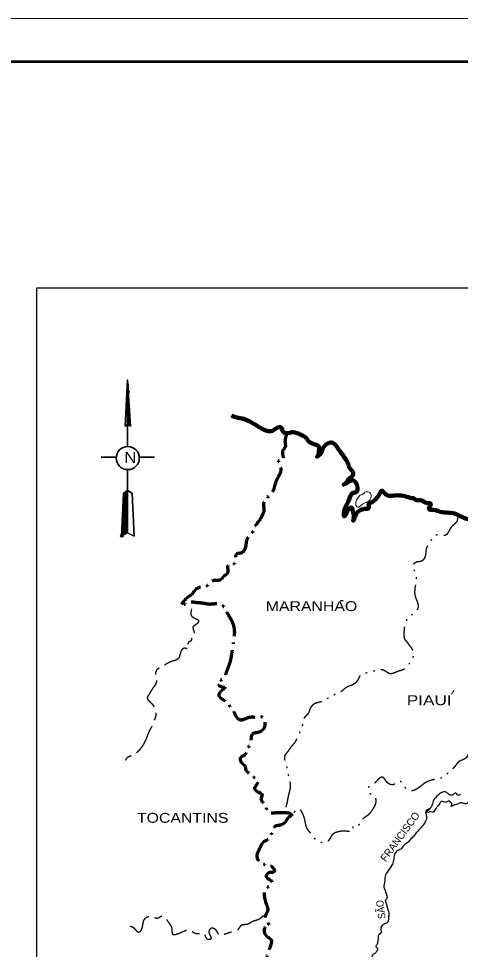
# Model space of a CAD drawing. Extents: x 512883 to 1063249, y 8784064 to 9081064.
# Drawn here: x 950481 to 1001709, y 8973228 to 9081064 of the extents above; entities that cross this region are included whole.
import ezdxf

# ---------------------------------------------------------------- set-up
doc = ezdxf.new("R2010")
doc.units = 0
doc.header["$LTSCALE"] = 600
doc.header["$PDMODE"] = 32
doc.header["$PDSIZE"] = 300
for name, pattern in [('DASH_DOUBLE_DOT', [9.2, 5, -1.2, 0.3, -1.2, 0.3, -1.2]), ('DOT_DASHED', [7.7, 5, -1.2, 0.3, -1.2]), ('LONG_DASH_SHORT_DASH', [9.9, 6, -1.2, 1.5, -1.2])]:
    doc.linetypes.add(name, pattern=pattern)
for name, color, linetype, lineweight in [('1', 7, 'Continuous', 25), ('3', 7, 'Continuous', 25), ('30', 7, 'Continuous', 25)]:
    doc.layers.add(name, color=color, linetype=linetype, lineweight=lineweight)

msp = doc.modelspace()

# ---------------------------------------------------------------- linework, layer by layer
at = {"layer": '1', "lineweight": 13}
for points in [[(512883.1, 8784063.9), (1063248.6, 8784063.9), (1063248.6, 9081063.9), (512883.1, 9081063.9)], [(537883.1, 9076063.9), (1058248.6, 9076063.9), (1058248.6, 8789063.9), (537883.1, 8789063.9)]]:
    msp.add_lwpolyline(points, close=True, dxfattribs=at)
at = {"layer": '1', "lineweight": 53}
msp.add_lwpolyline([(537883.1, 8789063.9), (1058248.6, 8789063.9), (1058248.6, 9076063.9), (537883.1, 9076063.9)], close=True, dxfattribs=at)
at = {"layer": '1'}
msp.add_lwpolyline([(537883.1, 9076063.9), (1058248.6, 9076063.9), (1058248.6, 8789063.9), (537883.1, 8789063.9)], close=True, dxfattribs=at)
at = {"layer": '3'}
msp.add_lwpolyline([(537883.1, 9076063.9), (1058248.6, 9076063.9), (1058248.6, 8789063.9), (537883.1, 8789063.9)], close=True, dxfattribs=at)
at = {"layer": '30'}
for p, q in [((963115.9, 9039189), (963170.4, 9037281.1)), ((963170.4, 9038698.4), (963170.4, 9037281.1)), ((963224.9, 9037281.1), (963170.4, 9038698.4)), ((963170.4, 9037826.2), (963170.4, 9037281.1)), ((963224.9, 9037281.1), (963170.4, 9037826.2)), ((963115.9, 9034010.5), (963443, 9033847)), ((962407.3, 9021091.6), (963115.9, 9021473.2)), ((963115.9, 9021473.2), (963879.1, 9021091.6)), ((998111.5, 8989475.7), (997675.4, 8989039.6))]:
    msp.add_line(p, q, dxfattribs=at)
at = {"layer": '30', "lineweight": 35}
for p, q in [((963170.4, 9037281.1), (963170.4, 9034065)), ((963170.4, 9037281.1), (963224.9, 9034065)), ((963170.4, 9037281.1), (963224.9, 9034065)), ((963334, 9033956), (963224.9, 9037281.1)), ((963388.5, 9033901.5), (963224.9, 9037281.1)), ((963115.9, 9031503), (963115.9, 9034010.5)), ((961807.7, 9030249.3), (960063.3, 9030249.3)), ((964478.7, 9030249.3), (966223, 9030249.3)), ((962625.3, 9026052), (962407.3, 9021091.6)), ((962461.8, 9021146.1), (962625.3, 9025943)), ((963115.9, 9026433.6), (962625.3, 9026052))]:
    msp.add_line(p, q, dxfattribs=at)
at = {"layer": '30', "lineweight": 13}
for p, q in [((963170.4, 9034065), (963388.5, 9033901.5)), ((963224.9, 9034065), (963334, 9033956)), ((963224.9, 9034065), (963334, 9034010.5)), ((963115.9, 9026433.6), (962625.3, 9026052)), ((962625.3, 9025943), (962679.8, 9025997.5)), ((963006.9, 9021527.7), (962625.3, 9021309.6)), ((962952.4, 9021527.7), (962679.8, 9021364.1)), ((962897.9, 9021527.7), (962734.3, 9021418.7)), ((962843.4, 9021527.7), (962788.8, 9021527.7)), ((963115.9, 9021473.2), (962516.3, 9021200.6)), ((963061.4, 9021473.2), (962570.8, 9021255.1))]:
    msp.add_line(p, q, dxfattribs=at)
at = {"layer": '30'}
msp.add_lwpolyline([(952595.4, 9049873), (1052567.1, 9049873), (1052567.1, 8921774), (952595.4, 8921774)], close=True, dxfattribs=at)
msp.add_lwpolyline([(952595.4, 9049873), (1052567.1, 9049873), (1052567.1, 8921774), (952595.4, 8921774)], close=True, dxfattribs=at)
at = {"layer": '30', "lineweight": 35}
for points in [[(963443, 9033847), (963115.9, 9039189), (962843.4, 9033847), (963115.9, 9034010.5), (963115.9, 9039189)], [(963334, 9034010.5), (963224.9, 9035863.8), (963279.4, 9034065)], [(963115.9, 9028832), (963115.9, 9026433.6), (963115.9, 9021473.2)], [(962516.3, 9021200.6), (962679.8, 9025943), (963115.9, 9026324.6), (963061.4, 9021473.2)], [(962570.8, 9021255.1), (962734.3, 9025943), (963061.4, 9026215.6), (963006.9, 9021527.7)], [(962625.3, 9021309.6), (962788.8, 9025943), (963006.9, 9026161), (962952.4, 9021527.7)], [(962679.8, 9025997.5), (963115.9, 9026379.1), (963115.9, 9021473.2)], [(962679.8, 9021364.1), (962843.4, 9025943), (962952.4, 9026052), (962897.9, 9021527.7)], [(962734.3, 9021418.7), (962843.4, 9025834), (962897.9, 9025943), (962843.4, 9021527.7)], [(962788.8, 9021527.7), (962843.4, 9025888.5), (963061.4, 9026270.1)], [(963879.1, 9021091.6), (963661, 9026052), (963115.9, 9026433.6)]]:
    msp.add_lwpolyline(points, dxfattribs=at)
at = {"layer": '30', "lineweight": 13}
for points in [[(963279.4, 9034065), (963334, 9034065), (963279.4, 9034228.6), (963170.4, 9034065)], [(962407.3, 9021091.6), (963115.9, 9021473.2), (962461.8, 9021146.1)]]:
    msp.add_lwpolyline(points, dxfattribs=at)
at = {"layer": '30', "lineweight": 35}
msp.add_circle((963141, 9030146.2), 1339.3, dxfattribs=at)
at = {"layer": '30', "lineweight": 140}
for points in [[(975162.7, 9035100.7), (975871.3, 9034828.2), (976470.9, 9034719.1), (977561.1, 9034228.6), (978106.2, 9033901.5), (978651.3, 9033574.4), (979305.4, 9033301.9), (979905.1, 9033301.9), (980395.6, 9033628.9), (980940.7, 9033683.4), (981158.8, 9033192.8), (981594.9, 9033029.3), (982194.5, 9033138.3), (982794.1, 9033029.3), (983284.7, 9032811.3), (983775.3, 9032538.7), (984047.8, 9032157.2), (984429.4, 9031884.6), (985029, 9031666.6), (985247, 9031557.6), (985301.6, 9031012.4), (985192.5, 9030467.3), (985083.5, 9030303.8), (985410.6, 9030576.4), (985683.1, 9031067), (985955.7, 9031557.6), (986446.3, 9031884.6), (986827.8, 9031939.1), (987263.9, 9031612.1), (987536.5, 9031230.5), (987863.5, 9030794.4), (988354.1, 9030085.8), (988681.2, 9029486.2), (988953.7, 9028886.6), (989226.3, 9028559.5), (989280.8, 9028232.4), (988899.2, 9027850.8), (988681.2, 9027632.8), (988354.1, 9027196.7), (988190.6, 9027087.7), (988681.2, 9027360.3), (989171.8, 9027578.3), (989444.3, 9027469.3), (989662.4, 9027142.2), (989771.4, 9026760.7), (989716.9, 9026270.1), (989280.8, 9026106.5), (988844.7, 9025506.9), (988681.2, 9025070.8), (988190.6, 9023762.6), (988245.1, 9023381), (988408.6, 9023599.1), (988790.2, 9024307.7), (989062.8, 9024416.7), (989226.3, 9024035.1), (989335.3, 9023653.6), (989335.3, 9023272), (989280.8, 9022890.4), (989498.8, 9023381), (989716.9, 9023817.1), (990153, 9024144.2), (990643.6, 9024253.2), (991079.6, 9024362.2), (991079.6, 9024798.3), (991515.7, 9025070.8), (991897.3, 9025397.9), (992333.4, 9025997.5), (992605.9, 9026379.1), (992987.5, 9025997.5), (993587.1, 9025779.5), (994404.8, 9025834), (995004.4, 9025779.5), (995385.9, 9025725)], [(995385.9, 9025670.5), (995658.5, 9025615.9), (996094.6, 9025506.9), (996258.1, 9025506.9), (996367.1, 9025452.4)], [(996367.1, 9025452.4), (996476.1, 9025343.4), (997184.8, 9025234.4), (997784.4, 9024961.8), (998275, 9024852.8), (998056.9, 9024253.2), (998602, 9024144.2), (999365.2, 9023926.1), (1000400.9, 9023817.1), (1001218.5, 9023653.6), (1001763.6, 9023381), (1002472.3, 9023108.5), (1003126.4, 9022999.5), (1003889.5, 9023163), (1004543.7, 9023217.5), (1005633.9, 9023381)]]:
    msp.add_spline(points, degree=3, dxfattribs=at)
at = {"layer": '30', "linetype": 'DOT_DASHED', "lineweight": 70}
for points in [[(981594.9, 9033029.3), (981376.8, 9031939.1), (981376.8, 9031394), (981158.8, 9031121.5), (981104.3, 9030521.8), (981049.8, 9029867.7), (980613.7, 9029813.2), (980722.7, 9029431.7), (980886.2, 9028886.6), (980777.2, 9028341.4), (980450.2, 9027741.8), (980232.1, 9027196.7), (980014.1, 9026433.6), (979687, 9025888.5), (979087.4, 9025397.9), (978869.3, 9024743.8), (978923.9, 9024144.2), (978760.3, 9023599.1), (978324.2, 9022835.9), (977888.2, 9022236.3), (977506.6, 9021418.7), (977016, 9020873.6), (976798, 9019892.4), (976252.9, 9019129.2), (975816.8, 9019074.7), (975598.7, 9018366.1), (975435.2, 9017875.5), (974781.1, 9017766.5), (974726.6, 9016894.3), (974236, 9016403.7), (973854.4, 9016022.1), (973200.3, 9015967.6), (972764.2, 9015804.1), (972273.6, 9015313.5), (971456, 9015150), (970965.4, 9014877.4), (970583.8, 9014386.8), (969820.7, 9013787.2), (969275.6, 9012969.6), (970147.7, 9013460.2), (970910.9, 9013460.2), (971946.6, 9013351.1), (972655.2, 9013242.1), (973309.3, 9013296.6), (974181.5, 9013024.1), (974726.6, 9012097.4), (975217.2, 9011225.2), (975489.7, 9010189.6), (975435.2, 9009208.4), (975162.7, 9007409.5), (974944.6, 9006373.8), (974563.1, 9005338.1), (974127, 9004520.5), (973527.3, 9004084.4), (973799.9, 9003757.3), (974399.5, 9003539.3), (973963.4, 9003157.7), (973690.9, 9002612.6), (974290.5, 9002122), (974999.1, 9001358.9), (975435.2, 9000759.3), (975871.3, 8999996.2), (976307.4, 8999832.6), (977125, 9000105.2), (978160.7, 9000159.7), (978760.3, 9000159.7), (979032.9, 8999560.1), (978814.8, 8998687.9), (978269.7, 8998360.8), (977615.6, 8998197.3), (977343.1, 8997052.6), (976907, 8996289.5), (976743.5, 8995798.9), (976198.3, 8995417.3), (976361.9, 8994817.7), (976743.5, 8994436.1), (976798, 8994054.5), (977343.1, 8993563.9), (977670.1, 8993236.9), (978160.7, 8992909.8), (978106.2, 8992364.7), (977833.7, 8991874.1), (978324.2, 8991438.1), (978705.8, 8991165.5), (978596.8, 8990674.9), (978760.3, 8990293.3), (979141.9, 8989857.2), (979250.9, 8989312.2), (980559.2, 8989094.1), (981267.8, 8989094.1), (981867.4, 8989039.6)], [(981867.4, 8989039.6), (982140, 8988821.6), (981758.4, 8988494.5), (981376.8, 8987949.4), (980831.7, 8987622.3), (980177.6, 8987458.8), (979850.5, 8986859.2), (979469, 8985987), (978869.3, 8985660), (978433.3, 8984951.3), (978106.2, 8984024.7), (978433.3, 8983316), (979196.4, 8983043.5), (979959.6, 8982716.4), (980123.1, 8982225.8), (979414.5, 8982062.3), (979196.4, 8981626.2), (979850.5, 8981081.1), (979741.5, 8980754.1), (979032.9, 8980154.4), (978978.4, 8979336.8), (979196.4, 8978464.6), (979359.9, 8977756), (979087.4, 8977101.9), (979359.9, 8976338.7), (979523.5, 8975902.6), (979196.4, 8975848.1), (979087.4, 8974921.5), (979741.5, 8974376.4), (979632.5, 8973504.2), (979305.4, 8972577.5), (979196.4, 8971759.9), (979359.9, 8971051.2), (979741.5, 8970288.1), (980286.6, 8969688.5), (980341.1, 8968707.3), (980068.6, 8967726.1), (979905.1, 8966690.4), (979850.5, 8966036.3), (979469, 8965164.1), (987645.5, 8970724.2), (988572.2, 8969415.9), (989389.8, 8969034.4), (989498.8, 8968380.2), (989716.9, 8967726.1), (990425.5, 8967344.5), (991079.6, 8966854), (991515.7, 8966690.4), (992224.3, 8967181), (992714.9, 8967617.1), (993205.5, 8967235.5), (993805.1, 8966963), (994568.3, 8966417.9), (995167.9, 8965872.8), (995658.5, 8965382.2), (996367.1, 8965109.6), (996803.2, 8965109.6), (997511.8, 8964673.5), (998166, 8965000.6), (999038.1, 8965000.6), (999746.8, 8964237.5), (1000291.9, 8963528.8), (1000673.4, 8962874.7), (1000782.5, 8962220.6), (1000837, 8961621), (1001218.5, 8961675.5), (1001872.7, 8961675.5), (1002744.8, 8961730), (1003562.5, 8961566.5), (1004162.1, 8961348.4), (1004816.2, 8961184.9), (1005524.8, 8961021.4), (1006069.9, 8960639.8), (1006560.5, 8960149.2), (1007051.1, 8959658.6), (1007214.7, 8959113.5), (1006996.6, 8958077.8), (1006506, 8957369.2), (1006124.5, 8956769.6), (1005361.3, 8956551.5), (1004816.2, 8955842.9), (1004271.1, 8954807.2), (1003944, 8953717), (1003944, 8953171.9), (1004434.6, 8952354.2), (1004925.2, 8951918.2), (1005252.3, 8951046), (1005906.4, 8950609.9), (1006506, 8949955.8), (1007214.7, 8949737.8), (1008195.8, 8949901.3)]]:
    msp.add_spline(points, degree=3, dxfattribs=at)
at = {"layer": '30', "lineweight": 13}
msp.add_spline([(990643.6, 9026215.6), (991079.6, 9026215.6), (991297.7, 9026052), (991243.2, 9025343.4), (990807.1, 9025016.3), (990207.5, 9024689.3), (989825.9, 9024471.2), (989662.4, 9024580.2), (989607.9, 9025125.3), (989771.4, 9025452.4), (990098.5, 9025834), (990371, 9025943), (990643.6, 9026215.6)], degree=3, dxfattribs=at)
at = {"layer": '30', "linetype": 'DASH_DOUBLE_DOT'}
for points in [[(1001382.1, 9023490), (1001273, 9022781.4), (1000891.5, 9022399.8), (1000455.4, 9021854.7), (999964.8, 9021200.6), (999419.7, 9021200.6), (998820.1, 9021200.6), (998384, 9020764.5), (998002.4, 9020164.9), (997729.9, 9019565.3), (997675.4, 9019020.2), (997184.8, 9018202.6), (996639.7, 9018093.5), (996149.1, 9017657.5), (996367.1, 9017112.3), (996585.2, 9016458.2), (996421.6, 9014332.3), (996694.2, 9013514.7), (996803.2, 9012969.6), (996530.7, 9012370), (995767.5, 9011770.3), (995167.9, 9009535.4), (995222.4, 9009208.4), (995495, 9008881.3), (995713, 9008554.2), (996040.1, 9008118.2), (996203.6, 9007082.5), (995985.6, 9006537.4), (995549.5, 9006101.3), (995222.4, 9005719.7), (994513.8, 9005447.2), (993532.6, 9005174.6), (992824, 9005556.2), (991951.8, 9005556.2), (991025.1, 9005283.6), (990153, 9005011.1), (989716.9, 9004302.5), (989171.8, 9003866.4), (988517.7, 9003593.8), (987754.5, 9002994.2), (987100.4, 9002721.7), (986282.7, 9002285.6), (985519.6, 9001904), (984811, 9001686), (984320.4, 9001195.4), (984047.8, 9000541.2), (983557.2, 8999941.6), (983502.7, 8999396.5), (983393.7, 8999233), (983175.7, 8998578.9), (982848.6, 8997924.8), (982576.1, 8997325.2), (981976.4, 8996562), (981594.9, 8996016.9), (981322.3, 8995635.3), (981376.8, 8995035.7), (981540.3, 8994490.6), (981703.9, 8993727.5), (981812.9, 8993127.9), (981921.9, 8992691.8), (981976.4, 8992092.2), (981812.9, 8991274.5), (981649.4, 8990511.4), (981485.8, 8989802.7), (981104.3, 8989094.1)], [(1002908.3, 8996180.4), (1002690.3, 8995962.4), (1002417.8, 8995471.8), (1001545.6, 8994981.2), (1001000.5, 8994327.1), (1000346.4, 8993727.5), (999801.3, 8993236.9), (998711.1, 8992909.8), (997729.9, 8992582.8), (996748.7, 8991874.1), (995931, 8991601.6), (995385.9, 8991874.1), (995058.9, 8992364.7), (994731.8, 8992691.8), (994077.7, 8992364.7), (993314.6, 8992473.7), (992605.9, 8993182.4), (992224.3, 8992964.3), (991461.2, 8992255.7), (991025.1, 8991983.2), (991134.2, 8991383.5), (991788.3, 8990892.9), (991897.3, 8990456.9), (991788.3, 8989911.8), (991570.2, 8989530.2), (990970.6, 8988767.1), (990316.5, 8988221.9), (989880.4, 8987622.3), (989280.8, 8987567.8), (989226.3, 8986968.2), (988517.7, 8986913.7), (987591, 8986859.2), (986882.3, 8986532.1), (986228.2, 8985660), (985410.6, 8985660), (984756.5, 8986150.6), (984429.4, 8986586.6), (983938.8, 8987240.8), (983720.8, 8988003.9), (983393.7, 8989039.6), (983012.1, 8989475.7), (982576.1, 8989257.6), (982194.5, 8988821.6)]]:
    msp.add_spline(points, degree=3, dxfattribs=at)
at = {"layer": '30', "linetype": 'LONG_DASH_SHORT_DASH'}
for points in [[(970529.3, 9012697), (970529.3, 9011879.4), (971019.9, 9011552.3), (971347, 9011334.3), (971019.9, 9010843.7), (970692.8, 9010571.1), (970801.8, 9009862.5), (970529.3, 9009589.9), (970474.8, 9008990.3), (970147.7, 9008772.3), (970147.7, 9008009.1), (969766.2, 9008118.2), (969221.1, 9007518.6), (969003, 9006918.9), (968403.4, 9006646.4), (967858.3, 9006428.3), (967313.2, 9006101.3), (966931.6, 9005883.2), (966495.5, 9005610.7), (966386.5, 9004793), (966441, 9004138.9), (966114, 9003593.8), (965568.9, 9002721.7), (965405.3, 9002394.6), (965950.4, 9001686), (966277.5, 9001031.8), (966386.5, 9000323.2), (966168.5, 8999723.6), (966005, 8999233), (965623.4, 8998524.4), (965350.8, 8997815.7), (965023.8, 8997107.1), (964587.7, 8996453), (964097.1, 8995962.4), (963497.5, 8995635.3), (963061.4, 8995417.3), (962734.3, 8994817.7)], [(978869.3, 8977156.4), (978269.7, 8976665.8), (977615.6, 8976447.7), (976961.5, 8976120.7), (976307.4, 8976011.7), (975871.3, 8975466.6), (975053.6, 8975194), (974399.5, 8974976), (973799.9, 8974867), (973418.3, 8975412.1), (973145.8, 8975630.1), (972873.2, 8975684.6), (972546.2, 8975248.5), (972764.2, 8974430.9), (972437.2, 8974376.4), (972001.1, 8975030.5), (971347, 8975030.5), (970801.8, 8975139.5), (970256.7, 8975466.6), (969766.2, 8975357.5), (969384.6, 8975194), (968839.5, 8974976), (968403.4, 8974921.5), (968294.4, 8975575.6), (968130.8, 8976011.7), (967749.3, 8976556.8), (967422.2, 8976938.3), (967095.2, 8977047.4), (966604.6, 8976829.3), (965950.4, 8976992.8), (965350.8, 8976938.3), (965023.8, 8976665.8), (964751.2, 8975630.1), (964424.2, 8975194), (963933.6, 8975630.1), (963443, 8975902.6)]]:
    msp.add_spline(points, degree=3, dxfattribs=at)
at = {"layer": '30'}
for points in [[(997675.4, 8989039.6), (997838.9, 8989148.6), (997947.9, 8989094.1), (998166, 8989203.1), (998438.5, 8989148.6), (998656.6, 8989203.1), (998983.6, 8989693.7), (999310.7, 8990075.3), (999528.7, 8990402.3), (999746.8, 8990347.8), (999964.8, 8990293.3), (1000237.3, 8990402.3), (1000400.9, 8990456.9), (1000509.9, 8990293.3), (1000673.4, 8990184.3), (1000618.9, 8989802.7), (1000946, 8989966.3), (1001109.5, 8990020.8), (1001491.1, 8990129.8), (1001818.1, 8990238.8), (1002036.2, 8990184.3), (1002417.8, 8990129.8), (1002744.8, 8990347.8), (1003071.9, 8990347.8), (1003398.9, 8990456.9), (1003617, 8990729.4), (1003726, 8991056.5), (1003780.5, 8991220), (1003944, 8991601.6), (1004107.6, 8991492.6), (1004271.1, 8991383.5), (1004598.2, 8991383.5), (1004816.2, 8991547.1), (1005088.8, 8991547.1), (1005361.3, 8991601.6)], [(1001709.1, 8991220), (1001491.1, 8991056.5), (1001164, 8991329), (1000782.5, 8991111), (1000346.4, 8991220), (1000073.8, 8991438.1), (999474.2, 8991383.5), (999147.1, 8991111), (998602, 8990511.4), (998438.5, 8989966.3), (998275, 8989639.2), (998220.5, 8989584.7)], [(1001709.1, 8991220), (1001491.1, 8991056.5), (1001164, 8991329), (1000782.5, 8991111), (1000346.4, 8991220), (1000073.8, 8991438.1), (999474.2, 8991383.5), (999147.1, 8991111), (998602, 8990511.4), (998438.5, 8989966.3), (998275, 8989639.2), (998220.5, 8989584.7)], [(998111.5, 8989475.7), (997784.4, 8989366.7), (997675.4, 8989094.1), (997784.4, 8988549), (997729.9, 8988221.9), (997457.3, 8987731.3), (997021.2, 8987186.2), (996694.2, 8986859.2), (996312.6, 8986368.6), (995931, 8985987), (995604, 8985605.5), (995167.9, 8985278.4), (994840.8, 8984896.8), (994459.3, 8984678.8), (994077.7, 8984242.7), (993968.7, 8983534.1), (993750.6, 8982989), (993205.5, 8982171.3), (992933, 8981571.7), (992933, 8981190.1), (992824, 8980427), (992987.5, 8980045.4), (993042, 8979827.4), (993205.5, 8979282.3), (993151, 8979064.2), (992987.5, 8978846.2), (993096.5, 8978573.6), (993205.5, 8978137.6), (993423.6, 8977319.9), (993369.1, 8976883.8), (993314.6, 8976447.7), (993042, 8976229.7), (992769.5, 8976120.7), (992496.9, 8975739.1), (992496.9, 8975466.6), (992551.4, 8975248.5), (992224.3, 8974867), (992169.8, 8974485.4), (992115.3, 8974103.8), (992060.8, 8973831.2), (991897.3, 8973558.7), (992115.3, 8973340.7), (992006.3, 8973013.6), (991788.3, 8972741.1), (991515.7, 8972577.5), (991461.2, 8971923.4), (991188.7, 8971378.3), (991025.1, 8970996.7), (990861.6, 8970560.6), (990698.1, 8970179.1), (990643.6, 8969743), (990425.5, 8969197.9), (990153, 8968816.3), (990043.9, 8968489.3), (989880.4, 8967998.7), (989771.4, 8967617.1), (989662.4, 8967290), (989498.8, 8966744.9), (989389.8, 8966145.3), (989171.8, 8965763.8), (988844.7, 8965436.7), (988572.2, 8965055.1), (988190.6, 8964564.5), (988136.1, 8964237.5), (987536.5, 8963692.4), (987263.9, 8963365.3), (986827.8, 8962874.7), (986500.8, 8962602.2), (986173.7, 8962329.6), (985901.2, 8962166.1), (985301.6, 8962166.1), (984974.5, 8961730), (984865.5, 8961348.4), (984483.9, 8961293.9), (984156.8, 8960912.3), (984156.8, 8959767.6)], [(998220.5, 8989584.7), (998220.5, 8989530.2), (998166, 8989530.2), (998111.5, 8989475.7)]]:
    msp.add_spline(points, degree=3, dxfattribs=at)
for p in [(963170.4, 9037826.2), (963224.9, 9034065), (962461.8, 9021146.1)]:
    msp.add_point(p, dxfattribs=at)

# ---------------------------------------------------------------- texts
for s, height, width, p in [('N ', 1256, 1.15, (962734.3, 9029595.2)), ('MARANHAO', 1144, 1.2, (979141.9, 9012424.5)), ('PIAUI', 1144, 1.3, (995495, 9001522.4)), ('TOCANTINS', 1144, 1.2, (964206.1, 8987894.9))]:
    msp.add_text(s, height=height, dxfattribs=dict(at, width=width)).set_placement(p)
msp.add_text('-', height=1144, dxfattribs=at).set_placement((987700, 9013187.6))
for s, height, rotation, width, p in [('-', 1144, 59.434, 1.5, (1001000.5, 9002449.1)), ('SÃO', 858.2, 97.54, 0.9, (993042, 8976829.3))]:
    msp.add_text(s, height=height, rotation=rotation, dxfattribs=dict(at, width=width)).set_placement(p)
msp.add_text('FRANCISCO', height=858.5, rotation=53.575, dxfattribs=at).set_placement((993042, 8983316))

doc.saveas('drawing.dxf')
